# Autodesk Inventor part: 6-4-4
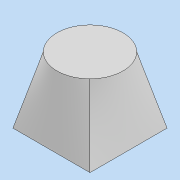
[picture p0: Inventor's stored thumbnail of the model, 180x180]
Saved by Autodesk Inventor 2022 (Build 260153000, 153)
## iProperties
Created: 2021-07
Part Number: 6-4-4
Material: 一般
Document SubType Name: Modeling
Designer: DesignLab
Density: 1 g/cm^3
Appearance: 既定
Author: DesignLab
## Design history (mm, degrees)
sketch "スケッチ1"
  geometry: L1 (-17.5, -17.5)-(17.5, -17.5); L2 (17.5, -17.5)-(17.5, 17.5); L3 (17.5, 17.5)-(-17.5, 17.5); L4 (-17.5, 17.5)-(-17.5, -17.5); L5 (-17.5, -17.5)-(17.5, 17.5); L6 (17.5, -17.5)-(-17.5, 17.5); 1 further point
  constraints: 12 end point, 2 midpoint, 2 parallel, 1 horizontal, 1 perpendicular
  dimensions: "d0" = 35 distance of L3.end L2.end; "d1" = 35 distance of L2.end L1.end
node "作業平面1"
sketch "スケッチ2"
  geometry: C1 r 15 at (0, 0); 1 further point
  constraints: 1 centre point, 1 coincident
  dimensions: "d3" = 30 diameter of C1
feature "ロフト1" sketch "スケッチ2" dims "d4" = 0, "d5" = 90 deg, "d6" = 0, "d7" = 90 deg
node "ソリッド1"
